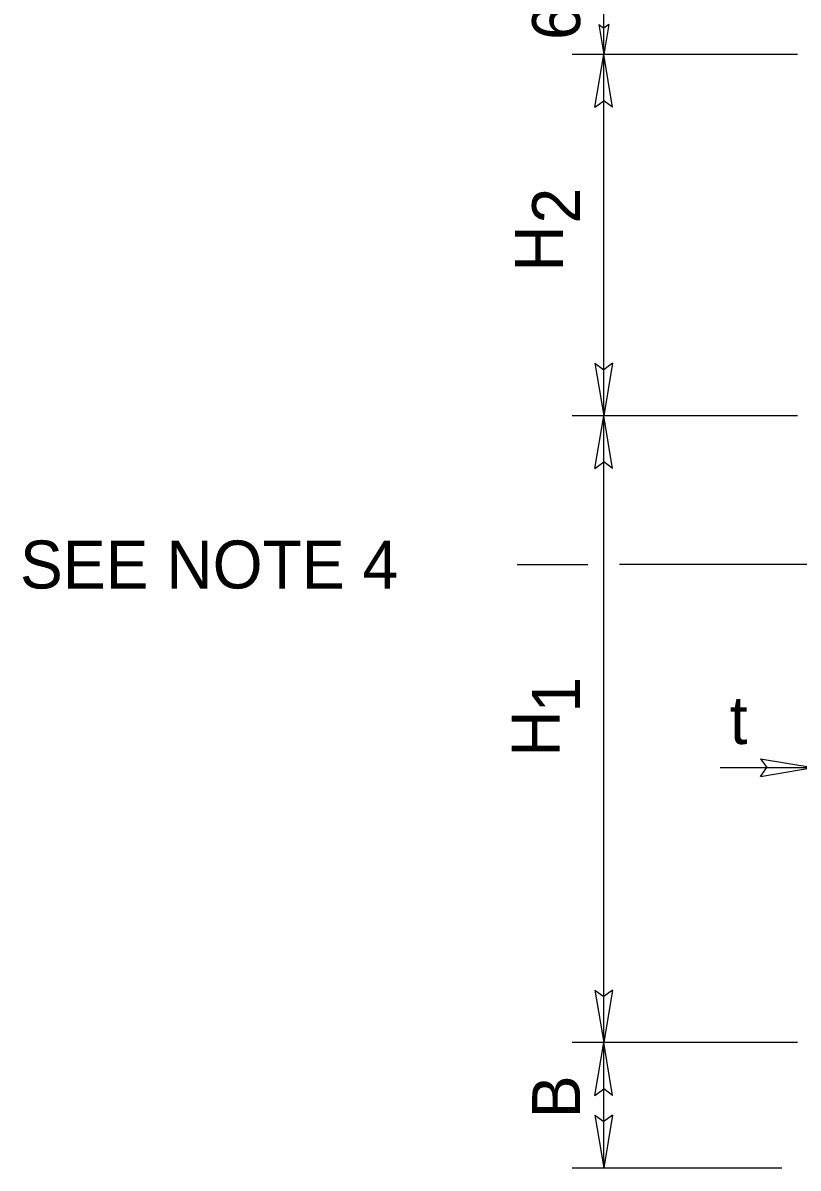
# Model space of a CAD drawing. Extents: x 5.8 to 18, y -5.2 to 5.4.
# Drawn here: x 5.892 to 6.86, y -2.132 to -0.7 of the extents above; entities that cross this region are included whole.
import ezdxf

# ---------------------------------------------------------------- set-up
doc = ezdxf.new("R2010")
doc.units = 0
doc.layers.add('DETL-DIMS', color=7, linetype='Continuous')
doc.layers.add('DETL-NOTE', color=7, linetype='Continuous')

msp = doc.modelspace()

# ---------------------------------------------------------------- linework, layer by layer
at = {"layer": 'DETL-DIMS'}
for p, q in [((6.6175, -0.7393), (6.6175, -0.6101)), ((6.6112, -0.7017), (6.6175, -0.7393)), ((6.6112, -0.7017), (6.6175, -0.7064)), ((6.6237, -0.7017), (6.6175, -0.7393)), ((6.6237, -0.7017), (6.6175, -0.7064)), ((6.8595, -0.7393), (6.5782, -0.7393)), ((6.6065, -0.8052), (6.6175, -0.7393)), ((6.6175, -1.1912), (6.6175, -0.7393)), ((6.6284, -0.8052), (6.6175, -0.7393)), ((6.6065, -0.8052), (6.6175, -0.797)), ((6.6284, -0.8052), (6.6175, -0.797)), ((6.6065, -1.1253), (6.6175, -1.1912)), ((6.6065, -1.1253), (6.6175, -1.1335)), ((6.6284, -1.1253), (6.6175, -1.1912)), ((6.6284, -1.1253), (6.6175, -1.1335)), ((6.8595, -1.1912), (6.5782, -1.1912)), ((6.6065, -1.2571), (6.6175, -1.1912)), ((6.6175, -1.9749), (6.6175, -1.1912)), ((6.6284, -1.2571), (6.6175, -1.1912)), ((6.6065, -1.2571), (6.6175, -1.2488)), ((6.6284, -1.2571), (6.6175, -1.2488)), ((6.5095, -1.377), (6.5978, -1.377)), ((6.9271, -1.377), (6.6371, -1.377)), ((6.7628, -1.6309), (6.8791, -1.6309)), ((6.8133, -1.6199), (6.8791, -1.6309)), ((6.8133, -1.6199), (6.8215, -1.6309)), ((6.8133, -1.6419), (6.8791, -1.6309)), ((6.8133, -1.6419), (6.8215, -1.6309)), ((6.6065, -1.9091), (6.6175, -1.9749)), ((6.6065, -1.9091), (6.6175, -1.9173)), ((6.6284, -1.9091), (6.6175, -1.9749)), ((6.6284, -1.9091), (6.6175, -1.9173)), ((6.8595, -1.9749), (6.5782, -1.9749)), ((6.6065, -2.0408), (6.6175, -1.9749)), ((6.6175, -2.1318), (6.6175, -1.9749)), ((6.6284, -2.0408), (6.6175, -1.9749)), ((6.6065, -2.0408), (6.6175, -2.0326)), ((6.6284, -2.0408), (6.6175, -2.0326)), ((6.6065, -2.0655), (6.6175, -2.1313)), ((6.6065, -2.0655), (6.6175, -2.0737)), ((6.6065, -2.0655), (6.6175, -2.1313)), ((6.6065, -2.0655), (6.6175, -2.0737)), ((6.6065, -2.0655), (6.6175, -2.1313)), ((6.6065, -2.0655), (6.6175, -2.0737)), ((6.6284, -2.0655), (6.6175, -2.1313)), ((6.6284, -2.0655), (6.6175, -2.0737)), ((6.6284, -2.0655), (6.6175, -2.1313)), ((6.6284, -2.0655), (6.6175, -2.0737)), ((6.6284, -2.0655), (6.6175, -2.1313)), ((6.6284, -2.0655), (6.6175, -2.0737)), ((6.8399, -2.1318), (6.5782, -2.1318))]:
    msp.add_line(p, q, dxfattribs=at)

# ---------------------------------------------------------------- texts
at = {"layer": 'DETL-NOTE'}
for s, p in [('6"', (6.588, -0.7211)), ('2', (6.588, -0.9506)), ('H', (6.5665, -1.0109)), ('1', (6.588, -1.5621)), ('H', (6.5623, -1.6174)), ('B', (6.588, -2.0693))]:
    msp.add_text(s, height=0.06, rotation=90, dxfattribs=at).set_placement(p)
for s, p in [('SEE NOTE 4', (5.888, -1.407)), ('t', (6.7749, -1.6015))]:
    msp.add_text(s, height=0.06, dxfattribs=at).set_placement(p)

doc.saveas('drawing.dxf')
